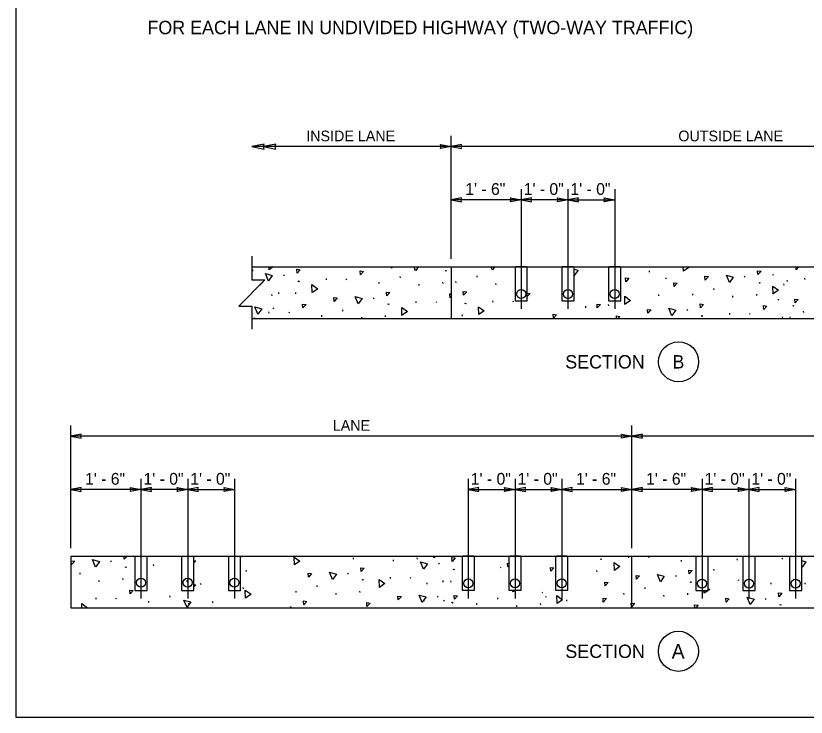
# Model space of a CAD drawing. Extents: x 99862 to 104211, y 98939 to 105076.
# Drawn here: x 99862 to 101045, y 100000 to 101049 of the extents above; entities that cross this region are included whole.
import ezdxf

# ---------------------------------------------------------------- set-up
doc = ezdxf.new("R2010")
doc.units = 0
for name, color, linetype in [('Level 1', 7, 'Continuous'), ('Level 15', 7, 'Continuous'), ('Level 20', 7, 'Continuous'), ('Level 3', 7, 'Continuous'), ('Level 4', 7, 'Continuous'), ('Level 60', 7, 'Continuous'), ('Level 9', 7, 'Continuous')]:
    doc.layers.add(name, color=color, linetype=linetype)

msp = doc.modelspace()

# ---------------------------------------------------------------- linework, layer by layer
at = {"layer": 'Level 1'}
for p, q in [((100215.3, 100673.3), (101353.6, 100673.3)), ((100513.6, 100673.3), (100513.6, 100596.3)), ((100215.3, 100596.3), (101353.6, 100596.3)), ((101624.4, 100240.2), (99944.4, 100240.2)), ((99944.4, 100240.2), (99944.4, 100163.2)), ((99944.4, 100163.2), (101624.4, 100163.2))]:
    msp.add_line(p, q, dxfattribs=at)
msp.add_lwpolyline([(99862, 99999.5), (103151, 99999.5), (103151, 102075.5), (99862, 102075.5)], close=True, dxfattribs=at)
at = {"layer": 'Level 15'}
for p, q in [((100513.6, 100685.3), (100513.6, 100869.3)), ((100513.6, 100853.3), (100215.3, 100853.3)), ((101353.6, 100853.3), (100513.6, 100853.3)), ((100618.6, 100789.9), (100618.6, 100610.5)), ((100688.6, 100789.9), (100688.6, 100610.5)), ((100758.6, 100789.9), (100758.6, 100610.5)), ((100618.6, 100773.9), (100513.6, 100773.9)), ((100688.6, 100773.9), (100618.6, 100773.9)), ((100688.6, 100773.9), (100758.6, 100773.9)), ((99944.4, 100252.2), (99944.4, 100436.2)), ((100784.4, 100252.2), (100784.4, 100436.2)), ((100784.4, 100420.2), (99944.4, 100420.2)), ((101624.4, 100420.2), (100784.4, 100420.2)), ((100049.4, 100356.2), (100049.4, 100177.2)), ((100119.4, 100356.2), (100119.4, 100177.2)), ((100189.4, 100356.2), (100189.4, 100177.2)), ((100539.4, 100356.2), (100539.4, 100177.2)), ((100609.4, 100356.2), (100609.4, 100177.2)), ((100679.4, 100356.2), (100679.4, 100177.2)), ((100889.4, 100356.2), (100889.4, 100177.2)), ((100959.4, 100356.2), (100959.4, 100177.2)), ((101029.4, 100356.2), (101029.4, 100177.2)), ((100049.4, 100340.2), (99944.4, 100340.2)), ((100119.4, 100340.2), (100049.4, 100340.2)), ((100119.4, 100340.2), (100189.4, 100340.2)), ((100539.4, 100340.2), (100609.4, 100340.2)), ((100609.4, 100340.2), (100679.4, 100340.2)), ((100679.4, 100340.2), (100784.4, 100340.2)), ((100889.4, 100340.2), (100784.4, 100340.2)), ((100959.4, 100340.2), (100889.4, 100340.2)), ((100959.4, 100340.2), (101029.4, 100340.2)), ((100784.4, 100163.2), (100784.4, 100240.2))]:
    msp.add_line(p, q, dxfattribs=at)
for points in [[(100215.3, 100853.3), (100233.6, 100849.7), (100232.8, 100853.3), (100233.6, 100856.9)], [(100232.8, 100853.3), (100251.1, 100849.7), (100250.3, 100853.3), (100251.1, 100856.9)], [(100513.6, 100853.3), (100497.8, 100850.3), (100498.6, 100853.3), (100497.8, 100856.4)], [(100513.6, 100853.3), (100529.3, 100850.3), (100528.6, 100853.3), (100529.3, 100856.4)], [(100513.6, 100773.9), (100529.3, 100770.8), (100528.6, 100773.9), (100529.3, 100776.9)], [(100618.6, 100773.9), (100602.8, 100770.8), (100603.6, 100773.9), (100602.8, 100776.9)], [(100618.6, 100773.9), (100634.3, 100770.8), (100633.6, 100773.9), (100634.3, 100776.9)], [(100688.6, 100773.9), (100672.8, 100770.8), (100673.6, 100773.9), (100672.8, 100776.9)], [(100688.6, 100773.9), (100704.3, 100770.8), (100703.6, 100773.9), (100704.3, 100776.9)], [(100758.6, 100773.9), (100742.8, 100770.8), (100743.6, 100773.9), (100742.8, 100776.9)], [(99944.4, 100420.2), (99960.1, 100417.1), (99959.4, 100420.2), (99960.1, 100423.2)], [(100784.4, 100420.2), (100768.7, 100417.1), (100769.4, 100420.2), (100768.7, 100423.2)], [(100784.4, 100420.2), (100800.1, 100417.1), (100799.4, 100420.2), (100800.1, 100423.2)], [(99944.4, 100340.2), (99960.1, 100337.1), (99959.4, 100340.2), (99960.1, 100343.2)], [(100049.4, 100340.2), (100033.7, 100337.1), (100034.4, 100340.2), (100033.7, 100343.2)], [(100049.4, 100340.2), (100065.1, 100337.1), (100064.4, 100340.2), (100065.1, 100343.2)], [(100119.4, 100340.2), (100103.7, 100337.1), (100104.4, 100340.2), (100103.7, 100343.2)], [(100119.4, 100340.2), (100135.1, 100337.1), (100134.4, 100340.2), (100135.1, 100343.2)], [(100189.4, 100340.2), (100173.7, 100337.1), (100174.4, 100340.2), (100173.7, 100343.2)], [(100539.4, 100340.2), (100555.1, 100337.1), (100554.4, 100340.2), (100555.1, 100343.2)], [(100609.4, 100340.2), (100593.7, 100337.1), (100594.4, 100340.2), (100593.7, 100343.2)], [(100609.4, 100340.2), (100625.1, 100337.1), (100624.4, 100340.2), (100625.1, 100343.2)], [(100679.4, 100340.2), (100663.7, 100337.1), (100664.4, 100340.2), (100663.7, 100343.2)], [(100679.4, 100340.2), (100695.1, 100337.1), (100694.4, 100340.2), (100695.1, 100343.2)], [(100784.4, 100340.2), (100768.7, 100337.1), (100769.4, 100340.2), (100768.7, 100343.2)], [(100784.4, 100340.2), (100800.1, 100337.1), (100799.4, 100340.2), (100800.1, 100343.2)], [(100889.4, 100340.2), (100873.7, 100337.1), (100874.4, 100340.2), (100873.7, 100343.2)], [(100889.4, 100340.2), (100905.1, 100337.1), (100904.4, 100340.2), (100905.1, 100343.2)], [(100959.4, 100340.2), (100943.7, 100337.1), (100944.4, 100340.2), (100943.7, 100343.2)], [(100959.4, 100340.2), (100975.1, 100337.1), (100974.4, 100340.2), (100975.1, 100343.2)], [(101029.4, 100340.2), (101013.7, 100337.1), (101014.4, 100340.2), (101013.7, 100343.2)]]:
    msp.add_lwpolyline(points, close=True, dxfattribs=at)
msp.add_lwpolyline([(100215.3, 100689.3), (100215.3, 100653.8), (100234.8, 100653.8), (100195.8, 100614.8), (100215.3, 100614.8), (100215.3, 100580.3)], dxfattribs=at)
at = {"layer": 'Level 3'}
msp.add_line((100118.2, 100201.9), (100119.3, 100204.6), dxfattribs=at)
for centre in [(100618.6, 100632.7), (100688.6, 100632.7), (100758.6, 100632.7), (100049.4, 100200.9), (100119.4, 100200.9), (100189.4, 100200.9), (100539.4, 100199.7), (100609.4, 100199.7), (100679.4, 100199.7), (100889.4, 100199.5), (100959.6, 100199.5), (101029.4, 100199.5)]:
    msp.add_circle(centre, 6.77, dxfattribs=at)
at = {"layer": 'Level 4'}
for p, q in [((100217, 100667.1), (100216.8, 100669.1)), ((100504.6, 100667.8), (100505.9, 100667.1)), ((100505.6, 100667.8), (100506.9, 100667.1)), ((100810.8, 100665.5), (100810.6, 100667.5)), ((100262.6, 100661.6), (100263.7, 100660)), ((100284.3, 100652.3), (100285.6, 100651.7)), ((100285.3, 100652.3), (100286.6, 100651.7)), ((100327.2, 100653.9), (100327, 100655.9)), ((100356.3, 100655.3), (100357.6, 100654.7)), ((100437.7, 100656.9), (100437.5, 100658.9)), ((100552.7, 100657.9), (100552.5, 100659.9)), ((100834.9, 100656.8), (100836, 100655.3)), ((100952.6, 100659.3), (100953.7, 100657.8)), ((100995.1, 100661.9), (100996.5, 100661.3)), ((101017.2, 100651.6), (101017, 100653.6)), ((101043.7, 100654.6), (101043.5, 100656.6)), ((100406.2, 100648.5), (100405.9, 100650.5)), ((100466, 100645.5), (100465.8, 100647.5)), ((100501.7, 100648.3), (100501.5, 100650.4)), ((100521.2, 100649.5), (100521, 100651.6)), ((100581.1, 100646.5), (100580.8, 100648.6)), ((100907.4, 100639.2), (100907.2, 100641.2)), ((100974.3, 100650), (100975.6, 100649.4)), ((100975.2, 100650), (100976.6, 100649.4)), ((101012.2, 100646.2), (101011.9, 100648.2)), ((100245.7, 100630), (100245.5, 100632.1)), ((100255.8, 100633), (100255.6, 100635.1)), ((100281.4, 100632.9), (100281.2, 100634.9)), ((100824.8, 100629.8), (100824.6, 100631.8)), ((100875.8, 100630.8), (100875.6, 100632.8)), ((100935.7, 100627.8), (100935.5, 100629.8)), ((100971.4, 100630.6), (100971.2, 100632.7)), ((100397, 100627.4), (100398.1, 100625.8)), ((100418.6, 100618.1), (100420, 100617.5)), ((100419.6, 100618.1), (100420.9, 100617.5)), ((100461.6, 100619.7), (100461.3, 100621.7)), ((100490.6, 100621.1), (100492, 100620.5)), ((100533.7, 100619.2), (100535, 100618.5)), ((100534.6, 100619.2), (100536, 100618.5)), ((100576.6, 100620.7), (100576.4, 100622.7)), ((100605.6, 100622.2), (100607, 100621.5)), ((100749.6, 100615.2), (100749.4, 100617.2)), ((101003, 100625.1), (101004.1, 100623.6)), ((100241.2, 100604.2), (100241, 100606.3)), ((100246.7, 100611.9), (100247.8, 100610.4)), ((100270.3, 100605.7), (100271.6, 100605)), ((100351.7, 100607.2), (100351.5, 100609.3)), ((100715.4, 100612.3), (100715.2, 100614.4)), ((100866.7, 100609.6), (100867.8, 100608.1)), ((101024.6, 100615.8), (101026, 100615.2)), ((101025.6, 100615.8), (101026.9, 100615.2)), ((101041.7, 100605), (101041.5, 100607)), ((100320.2, 100598.8), (100320, 100600.9)), ((100380, 100596.3), (100379.9, 100597.9)), ((100415.7, 100598.7), (100415.5, 100600.7)), ((100530.8, 100599.8), (100530.6, 100601.8)), ((100888.3, 100600.4), (100889.7, 100599.8)), ((100889.3, 100600.4), (100890.6, 100599.8)), ((100931.2, 100601.9), (100931, 100604)), ((100960.3, 100603.4), (100961.6, 100602.7)), ((101010.2, 100596.6), (101010, 100598.6)), ((101021.7, 100596.4), (101021.5, 100598.5)), ((100367.7, 100235.9), (100367.5, 100238)), ((100779.7, 100238), (100779.5, 100240)), ((100808.8, 100239.4), (100810.1, 100238.8)), ((100003.9, 100233.6), (100005, 100232.1)), ((100068.4, 100225.9), (100068.2, 100227.9)), ((100427.6, 100232.9), (100427.3, 100235)), ((100463.2, 100235.8), (100463, 100237.8)), ((100494.8, 100230.2), (100495.9, 100228.7)), ((100736.8, 100236.4), (100738.1, 100235.8)), ((100737.8, 100236.4), (100739.1, 100235.8)), ((100858.7, 100232.6), (100858.4, 100234.6)), ((100942.4, 100234.7), (100942.2, 100236.7)), ((101008.6, 100237.5), (101009.7, 100235.9)), ((99958.6, 100213.5), (99958.4, 100215.5)), ((100025.5, 100224.3), (100026.9, 100223.7)), ((100026.5, 100224.3), (100027.8, 100223.7)), ((100207.3, 100217.5), (100207, 100219.5)), ((100358.5, 100214.8), (100359.6, 100213.3)), ((100516.5, 100221), (100517.8, 100220.3)), ((100517.4, 100221), (100518.8, 100220.3)), ((100586.9, 100224), (100588.3, 100223.3)), ((100732.3, 100217), (100732.1, 100219.1)), ((100907.3, 100219.2), (100907.1, 100221.2)), ((99986.9, 100202.1), (99986.7, 100204.1)), ((100022.6, 100204.9), (100022.4, 100207)), ((100380.2, 100205.6), (100381.5, 100204.9)), ((100381.1, 100205.6), (100382.5, 100204.9)), ((100423.1, 100207.1), (100422.9, 100209.1)), ((100452.1, 100208.6), (100453.5, 100207.9)), ((100502, 100201.7), (100501.8, 100203.8)), ((100513.6, 100201.6), (100513.4, 100203.6)), ((100849.5, 100211.5), (100850.6, 100210)), ((100943.1, 100205.2), (100944.5, 100204.6)), ((100138.2, 100199.4), (100139.3, 100197.9)), ((100202.8, 100191.7), (100202.6, 100193.7)), ((100313.3, 100194.7), (100313, 100196.7)), ((100477.9, 100198.7), (100477.7, 100200.8)), ((100804.2, 100191.4), (100804, 100193.4)), ((100871.2, 100202.2), (100872.5, 100201.6)), ((100872.1, 100202.2), (100873.4, 100201.6)), ((100993, 100198.4), (100992.8, 100200.4)), ((101043.8, 100198.6), (101043.6, 100200.6)), ((100092.9, 100179.3), (100092.7, 100181.3)), ((100281.7, 100186.3), (100281.5, 100188.3)), ((100341.6, 100183.3), (100341.4, 100185.3)), ((100377.3, 100186.2), (100377.1, 100188.2)), ((100492.9, 100180.6), (100494, 100179.1)), ((100649.3, 100186.8), (100650.6, 100186.1)), ((100654.5, 100180.2), (100655.9, 100179.5)), ((100772.7, 100183), (100772.5, 100185)), ((100832.6, 100180), (100832.4, 100182)), ((100868.2, 100182.8), (100868, 100184.9)), ((99982.5, 100176.2), (99982.3, 100178.3)), ((100011.5, 100177.7), (100012.9, 100177)), ((100061.4, 100170.9), (100061.2, 100172.9)), ((100121.3, 100167.9), (100121.1, 100169.9)), ((100157, 100170.7), (100156.8, 100172.8)), ((100473.4, 100172.9), (100473.2, 100174.9)), ((100502.5, 100174.4), (100503.8, 100173.7)), ((100514.5, 100171.4), (100515.9, 100170.7)), ((100515.5, 100171.4), (100516.8, 100170.7)), ((100552.4, 100167.5), (100552.2, 100169.6)), ((100583.9, 100175.9), (100583.7, 100178)), ((100647.9, 100167.4), (100647.7, 100169.4)), ((100687, 100173), (100686.8, 100175)), ((100983.8, 100177.3), (100985, 100175.8)), ((101005.5, 100168), (101006.8, 100167.4)), ((101006.5, 100168.1), (101007.8, 100167.4)), ((100272.6, 100165.2), (100273.7, 100163.7)), ((100612.3, 100164.5), (100612, 100166.6))]:
    msp.add_line(p, q, dxfattribs=at)
for points in [[(100241.4, 100669.2), (100241.3, 100673.3)], [(100247.4, 100673.3), (100241.6, 100669.3)], [(100283, 100664), (100282.6, 100669.8), (100287.7, 100669.1), (100283, 100664)], [(100377.8, 100661.5), (100377.4, 100667.3), (100382.5, 100666.6), (100377.8, 100661.5)], [(100424.5, 100671.4), (100424.4, 100673.3)], [(100426.3, 100673.3), (100424.5, 100671.4)], [(100460.6, 100667.6), (100458.3, 100673.3)], [(100464.6, 100673.3), (100460.7, 100667.8)], [(100539.6, 100672.5), (100539.5, 100673.3)], [(100540.4, 100673.3), (100539.6, 100672.5)], [(100575.6, 100668.7), (100573.7, 100673.3)], [(100578.9, 100673.3), (100575.7, 100668.8)], [(100697.8, 100670.1), (100703.8, 100668.4), (100698.1, 100660.4)], [(100861.4, 100666.9), (100861.2, 100673.3)], [(100868.6, 100673.3), (100869.6, 100672.6), (100861.6, 100667)], [(100973, 100661.8), (100972.6, 100667.5), (100977.7, 100666.9), (100973, 100661.8)], [(101030.5, 100669.1), (101030.2, 100673.3)], [(101034.4, 100673.3), (101030.5, 100669.1)], [(100240.3, 100652.2), (100235.8, 100663.3), (100246, 100660.3), (100240.4, 100652.3)], [(100698, 100660.3), (100697.8, 100660.8)], [(100775.1, 100651.2), (100774.6, 100656.9), (100779.8, 100656.3), (100775.1, 100651.2)], [(100894.2, 100653.7), (100893.8, 100659.4), (100898.9, 100658.8), (100894.2, 100653.7)], [(100930.3, 100649.9), (100925.8, 100661), (100936, 100658.1), (100930.4, 100650.1)], [(100232.2, 100651.2), (100232.2, 100651.2), (100227.5, 100646.1)], [(100227.5, 100646.1), (100227.5, 100646.5)], [(100305.8, 100635), (100305.3, 100647), (100314, 100640.7), (100306, 100635.1)], [(100847.5, 100643.8), (100847, 100649.5), (100852.2, 100648.9), (100847.5, 100643.8)], [(100995.8, 100632.7), (100995.3, 100644.7), (101004, 100638.4), (100995.9, 100632.8)], [(100374.6, 100618), (100370.1, 100629.1), (100380.4, 100626.1), (100374.8, 100618.1)], [(100417.4, 100629.8), (100417, 100635.6), (100422.1, 100634.9), (100417.4, 100629.8)], [(100512.1, 100627.3), (100511.7, 100633.1), (100513.8, 100632.8)], [(100513.9, 100629.2), (100512.1, 100627.3)], [(100532.4, 100630.9), (100532, 100636.6), (100537.1, 100636), (100532.4, 100630.9)], [(100627.8, 100634), (100631.9, 100633.5), (100627.8, 100629.1)], [(100774, 100617.3), (100773.6, 100629.3), (100782.2, 100623), (100774.2, 100617.4)], [(100291.8, 100611.9), (100291.4, 100617.6), (100296.5, 100617), (100291.8, 100611.9)], [(100338.6, 100621.8), (100338.1, 100627.5), (100343.3, 100626.9), (100338.6, 100621.8)], [(100732.6, 100611.9), (100732.2, 100617.6), (100737.3, 100617), (100732.6, 100611.9)], [(100887.1, 100612.1), (100886.6, 100617.9), (100891.8, 100617.2), (100887.1, 100612.1)], [(101028.6, 100619.5), (101028.1, 100625.2), (101033.3, 100624.6), (101028.6, 100619.5)], [(100224.3, 100602.6), (100219.8, 100613.6), (100230.1, 100610.7), (100224.4, 100602.7)], [(100440.1, 100600.8), (100439.7, 100612.8), (100448.3, 100606.5), (100440.3, 100600.9)], [(100555.2, 100601.9), (100554.7, 100613.8), (100563.4, 100607.6), (100555.3, 100602)], [(100808.3, 100604.1), (100807.8, 100609.8), (100813, 100609.2), (100808.3, 100604.1)], [(100844.3, 100600.3), (100839.8, 100611.4), (100850.1, 100608.4), (100844.4, 100600.4)], [(100981.8, 100609.6), (100981.4, 100615.4), (100986.5, 100614.7), (100981.8, 100609.6)], [(100219.4, 100596.3), (100219.4, 100597.3), (100220.8, 100596.3)], [(100666.8, 100596.7), (100666.3, 100602.4), (100671.5, 100601.8), (100666.8, 100596.7)], [(100761.4, 100596.3), (100761.1, 100599.9), (100766.2, 100599.3), (100763.5, 100596.3)], [(100024.3, 100236.1), (100024, 100240.2)], [(100028, 100240.2), (100024.3, 100236.1)], [(100201.8, 100239.6), (100201.6, 100240.2)], [(100202.2, 100240.2), (100201.9, 100239.8)], [(100279.2, 100227.3), (100278.8, 100239.2), (100287.4, 100232.9), (100279.4, 100227.4)], [(100487.6, 100237.9), (100487.5, 100240.2)], [(100490.9, 100240.2), (100487.8, 100238)], [(100515.2, 100232.7), (100514.8, 100238.5), (100519.9, 100237.8), (100515.2, 100232.7)], [(100655.2, 100240.1), (100655.2, 100240.2)], [(100655.2, 100240.2), (100655.2, 100240.1)], [(99945.5, 100228), (99945, 100233.7), (99950.2, 100233.1), (99945.5, 100228)], [(99981.5, 100224.2), (99977, 100235.3), (99987.3, 100232.3), (99981.6, 100224.4)], [(100128.6, 100233.7), (100131.4, 100233.4), (100128.6, 100230.4)], [(100472.5, 100220.9), (100468, 100231.9), (100478.2, 100229), (100472.6, 100221)], [(100598.4, 100224.3), (100598, 100230), (100600.2, 100229.7)], [(100600.2, 100226.2), (100598.4, 100224.3)], [(100758.3, 100219.1), (100757.8, 100231.1), (100766.5, 100224.8), (100758.5, 100219.2)], [(101038.6, 100233.9), (101044.9, 100232.1), (101039.3, 100224.1)], [(100300.1, 100209.2), (100299.7, 100215), (100304.8, 100214.3), (100300.1, 100209.2)], [(100336.2, 100205.4), (100331.7, 100216.5), (100341.9, 100213.6), (100336.3, 100205.6)], [(100378.9, 100217.3), (100378.5, 100223), (100383.6, 100222.4), (100378.9, 100217.3)], [(100662.8, 100218), (100662.4, 100223.7), (100667.5, 100223.1), (100662.8, 100218)], [(100869.9, 100214), (100869.5, 100219.7), (100874.6, 100219.1), (100869.9, 100214)], [(101039.2, 100224), (101038.6, 100225.3)], [(100406.4, 100193.7), (100406, 100205.6), (100414.6, 100199.4), (100406.6, 100193.8)], [(100791.1, 100205.9), (100790.6, 100211.6), (100795.8, 100211), (100791.1, 100205.9)], [(100827.1, 100202.1), (100822.6, 100213.2), (100832.9, 100210.3), (100827.3, 100202.3)], [(100128.6, 100198), (100131.3, 100197.6), (100128.6, 100194.7)], [(100744.3, 100196), (100743.9, 100201.7), (100749, 100201.1), (100744.3, 100196)], [(100898.6, 100192.2), (100900.8, 100190.6), (100892.8, 100185)], [(100033.1, 100183.9), (100032.6, 100189.7), (100037.8, 100189), (100033.1, 100183.9)], [(100206, 100177.7), (100205.5, 100189.7), (100214.2, 100183.4), (100206.1, 100177.8)], [(100434.5, 100175), (100434, 100180.8), (100439.2, 100180.2), (100434.5, 100175)], [(100470.5, 100171.2), (100466, 100182.3), (100476.3, 100179.4), (100470.6, 100171.4)], [(100518.6, 100175.9), (100518.2, 100181.6), (100523.3, 100181), (100518.6, 100175.9)], [(100606.8, 100186.7), (100605.7, 100189.4)], [(100608.8, 100189.4), (100607, 100186.8)], [(100672.3, 100169.5), (100671.9, 100181.5), (100680.5, 100175.2), (100672.5, 100169.6)], [(100892.6, 100184.9), (100892.5, 100189.3)], [(100961.5, 100167.9), (100957, 100179), (100967.2, 100176.1), (100961.6, 100168.1)], [(101004.2, 100179.8), (101003.8, 100185.5), (101009, 100184.9), (101004.2, 100179.8)], [(99960.8, 100163.2), (99960.6, 100169.4), (99969.2, 100163.2)], [(100118.3, 100163.7), (100113.8, 100174.8), (100124.1, 100171.9), (100118.5, 100163.9)], [(100293, 100167.7), (100292.5, 100173.4), (100297.7, 100172.8), (100293, 100167.7)], [(100387.7, 100165.2), (100387.3, 100170.9), (100392.4, 100170.3), (100387.7, 100165.2)], [(100741.6, 100171.8), (100741.2, 100177.5), (100746.3, 100176.9), (100741.6, 100171.8)], [(100783.9, 100164.3), (100783.5, 100170.1), (100788.6, 100169.4), (100783.9, 100164.3)], [(100878.6, 100163.2), (100878.3, 100167.6), (100883.4, 100166.9), (100879.9, 100163.2)], [(100925.4, 100171.7), (100925, 100177.4), (100930.1, 100176.8), (100925.4, 100171.7)], [(100736.8, 100163.2), (100736.7, 100163.6), (100738.1, 100163.2)]]:
    msp.add_lwpolyline(points, dxfattribs=at)
at = {"layer": 'Level 60'}
msp.add_line((99862, 99999.5), (99862, 99999.5), dxfattribs=at)
at = {"layer": 'Level 9'}
for p, q in [((100609.4, 100672.2), (100609.4, 100638.6)), ((100626.6, 100673.3), (100610.5, 100673.3)), ((100627.8, 100638.6), (100627.8, 100672.2)), ((100679.4, 100672.2), (100679.4, 100638.6)), ((100696.6, 100673.3), (100680.5, 100673.3)), ((100697.8, 100638.6), (100697.8, 100672.2)), ((100749.4, 100672.2), (100749.4, 100638.6)), ((100766.6, 100673.3), (100750.5, 100673.3)), ((100767.8, 100638.6), (100767.8, 100672.2)), ((100609.4, 100638.6), (100609.4, 100622.5)), ((100627.8, 100622.5), (100627.8, 100638.6)), ((100679.4, 100638.6), (100679.4, 100622.5)), ((100697.8, 100622.5), (100697.8, 100638.6)), ((100749.4, 100638.6), (100749.4, 100622.5)), ((100767.8, 100622.5), (100767.8, 100638.6)), ((100609.4, 100622.5), (100627.8, 100622.5)), ((100679.4, 100622.5), (100697.8, 100622.5)), ((100749.4, 100622.5), (100767.8, 100622.5)), ((100040.2, 100238.9), (100040.2, 100205.3)), ((100057.5, 100240.1), (100041.4, 100240.1)), ((100058.6, 100205.3), (100058.6, 100238.9)), ((100110.2, 100238.9), (100110.2, 100205.3)), ((100127.5, 100240.1), (100111.4, 100240.1)), ((100128.6, 100205.3), (100128.6, 100238.9)), ((100180.2, 100238.9), (100180.2, 100205.3)), ((100197.5, 100240.1), (100181.4, 100240.1)), ((100198.6, 100205.3), (100198.6, 100238.9)), ((100530.2, 100239.1), (100530.2, 100205.5)), ((100547.5, 100240.3), (100531.4, 100240.3)), ((100548.6, 100205.5), (100548.6, 100239.1)), ((100600.2, 100239.1), (100600.2, 100205.5)), ((100617.5, 100240.3), (100601.4, 100240.3)), ((100618.6, 100205.5), (100618.6, 100239.1)), ((100670.2, 100239.1), (100670.2, 100205.5)), ((100687.5, 100240.3), (100671.4, 100240.3)), ((100688.6, 100205.5), (100688.6, 100239.1)), ((100880.2, 100239), (100880.2, 100205.4)), ((100897.5, 100240.1), (100881.4, 100240.1)), ((100898.6, 100205.4), (100898.6, 100239)), ((100950.4, 100239), (100950.4, 100205.4)), ((100967.7, 100240.1), (100951.6, 100240.1)), ((100968.9, 100205.4), (100968.9, 100239)), ((101020.2, 100239), (101020.2, 100205.4)), ((101037.5, 100240.1), (101021.4, 100240.1)), ((101038.6, 100205.4), (101038.6, 100239)), ((100040.2, 100205.3), (100040.2, 100189.2)), ((100058.6, 100189.2), (100058.6, 100205.3)), ((100110.2, 100205.3), (100110.2, 100189.2)), ((100128.6, 100189.2), (100128.6, 100205.3)), ((100180.2, 100205.3), (100180.2, 100189.2)), ((100198.6, 100189.2), (100198.6, 100205.3)), ((100530.2, 100205.5), (100530.2, 100189.4)), ((100548.6, 100189.4), (100548.6, 100205.5)), ((100600.2, 100205.5), (100600.2, 100189.4)), ((100618.6, 100189.4), (100618.6, 100205.5)), ((100670.2, 100205.5), (100670.2, 100189.4)), ((100688.6, 100189.4), (100688.6, 100205.5)), ((100880.2, 100205.4), (100880.2, 100189.3)), ((100898.6, 100189.3), (100898.6, 100205.4)), ((100950.4, 100205.4), (100950.4, 100189.3)), ((100968.9, 100189.3), (100968.9, 100205.4)), ((101020.2, 100205.4), (101020.2, 100189.3)), ((101038.6, 100189.3), (101038.6, 100205.4)), ((100040.2, 100189.2), (100058.6, 100189.2)), ((100110.2, 100189.2), (100128.6, 100189.2)), ((100180.2, 100189.2), (100198.6, 100189.2)), ((100530.2, 100189.4), (100548.6, 100189.4)), ((100600.2, 100189.4), (100618.6, 100189.4)), ((100670.2, 100189.4), (100688.6, 100189.4)), ((100880.2, 100189.3), (100898.6, 100189.3)), ((100950.4, 100189.3), (100968.9, 100189.3)), ((101020.2, 100189.3), (101038.6, 100189.3))]:
    msp.add_line(p, q, dxfattribs=at)
for centre in [(100854.2, 100531.3), (100854, 100098.1)]:
    msp.add_circle(centre, 30, dxfattribs=at)
for centre, start, end in [((100610.5, 100672.2), 90, 180), ((100626.6, 100672.2), 0, 90), ((100680.5, 100672.2), 90, 180), ((100696.6, 100672.2), 0, 90), ((100750.5, 100672.2), 90, 180), ((100766.6, 100672.2), 0, 90), ((100041.4, 100238.9), 90, 180), ((100057.5, 100238.9), 0, 90), ((100111.4, 100238.9), 90, 180), ((100127.5, 100238.9), 0, 90), ((100181.4, 100238.9), 90, 180), ((100197.5, 100238.9), 0, 90), ((100531.4, 100239.1), 90, 180), ((100547.5, 100239.1), 0, 90), ((100601.4, 100239.1), 90, 180), ((100617.5, 100239.1), 0, 90), ((100671.4, 100239.1), 90, 180), ((100687.5, 100239.1), 0, 90), ((100881.4, 100239), 90, 180), ((100897.5, 100239), 0, 90), ((100951.6, 100239), 90, 180), ((100967.7, 100239), 0, 90), ((101021.4, 100239), 90, 180), ((101037.5, 100239), 0, 90)]:
    msp.add_arc(centre, 1.17, start, end, dxfattribs=at)

# ---------------------------------------------------------------- texts
at = {"layer": 'Level 20'}
for s, height, p in [(' FOR EACH LANE IN UNDIVIDED HIGHWAY (TWO-WAY TRAFFIC)', 20, (100051.6, 101021.6)), ('INSIDE LANE', 16, (100296.8, 100861.3)), ('OUTSIDE LANE', 16, (100853.9, 100861.3)), ('1\' - 6"', 17.6, (100534.9, 100781.1)), ('1\' - 0"', 17.6, (100622.4, 100781.1)), ('1\' - 0"', 17.6, (100692.4, 100781.1)), ('SECTION', 20, (100684.6, 100521.3)), ('B', 20, (100845, 100521.3)), ('LANE', 16, (100336.6, 100428.2)), ('1\' - 6"', 17.6, (99965.7, 100347.4)), ('1\' - 0"', 17.6, (100053.2, 100347.4)), ('1\' - 0"', 17.6, (100123.2, 100347.4)), ('1\' - 0"', 17.6, (100543.2, 100347.4)), ('1\' - 0"', 17.6, (100613.2, 100347.4)), ('1\' - 6"', 17.6, (100700.7, 100347.4)), ('1\' - 6"', 17.6, (100805.7, 100347.4)), ('1\' - 0"', 17.6, (100893.2, 100347.4)), ('1\' - 0"', 17.6, (100963.2, 100347.4)), ('SECTION', 20, (100684.8, 100088.1)), ('A', 21.6, (100844, 100087.3))]:
    msp.add_text(s, height=height, dxfattribs=at).set_placement(p)

doc.saveas('drawing.dxf')
